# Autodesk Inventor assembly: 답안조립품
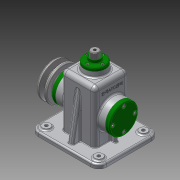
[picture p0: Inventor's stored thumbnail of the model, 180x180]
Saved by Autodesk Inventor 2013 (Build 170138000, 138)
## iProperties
Created: 2016-01
Part Number: 답안조립품
Document SubType Name: Assembly
Designer: User
Author: User
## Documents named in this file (19)
- C:\Users\User\Desktop\460126V1002\답안조립품.iam
- C:\Users\User\Desktop\460126V1002\본체.ipt
- C:\Users\User\Desktop\460126V1002\뒤커버.ipt
- C:\Users\User\Desktop\460126V1002\앞커버.ipt
- C:\Users\User\Desktop\460126V1002\상부부시.ipt
- C:\Users\User\Desktop\460126V1002\베어링 15 x 35 x 11.ipt
- C:\Users\User\Desktop\460126V1002\편심축.ipt
- C:\Users\User\Desktop\460126V1002\키 5 x 5 x 14.ipt
- C:\Users\User\Desktop\460126V1002\와셔.ipt
- C:\Users\User\Desktop\460126V1002\멈춤링 15 x 1.ipt
- C:\Users\User\Desktop\460126V1002\V-벨트풀리.ipt
- C:\Users\User\Desktop\460126V1002\고정핀.ipt
- C:\Users\User\Desktop\460126V1002\슬라이드바.ipt
- C:\Users\User\Desktop\460126V1002\링크.ipt
- C:\Users\User\Desktop\460126V1002\멈춤링 6 x 5.ipt
- C:\Users\User\Desktop\460126V1002\오일실 15 25 7.ipt
- C:\Users\User\Desktop\460126V1002\볼트 M4 x 10.ipt
- C:\Users\User\Desktop\460126V1002\볼트 M3 x 8.ipt
- C:\Users\User\Desktop\460126V1002\볼트 M6 x 12.ipt
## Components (15 placed, 5 different names)
1. V-벨트풀리:1
2. 고정핀:1
3. ISO 4018 M6 x 12:1 — 각도:1
4. ISO 4762 M4 x 10:1
5. ISO 4762 M4 x 10:2
6. ISO 4762 M4 x 10:3
7. ISO 4762 M4 x 10:4
8. ISO 4762 M4 x 10:5
9. ISO 4762 M4 x 10:6
10. ISO 4762 M4 x 10:7
11. ISO 4762 M4 x 10:8
12. ISO 4762 M3 x 8:1
13. ISO 4762 M3 x 8:2
14. ISO 4762 M3 x 8:3
15. ISO 4762 M3 x 8:4
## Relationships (1: Angle 1)
- 각도:1 [Angle]: ISO 4018 M6 x 12:1
